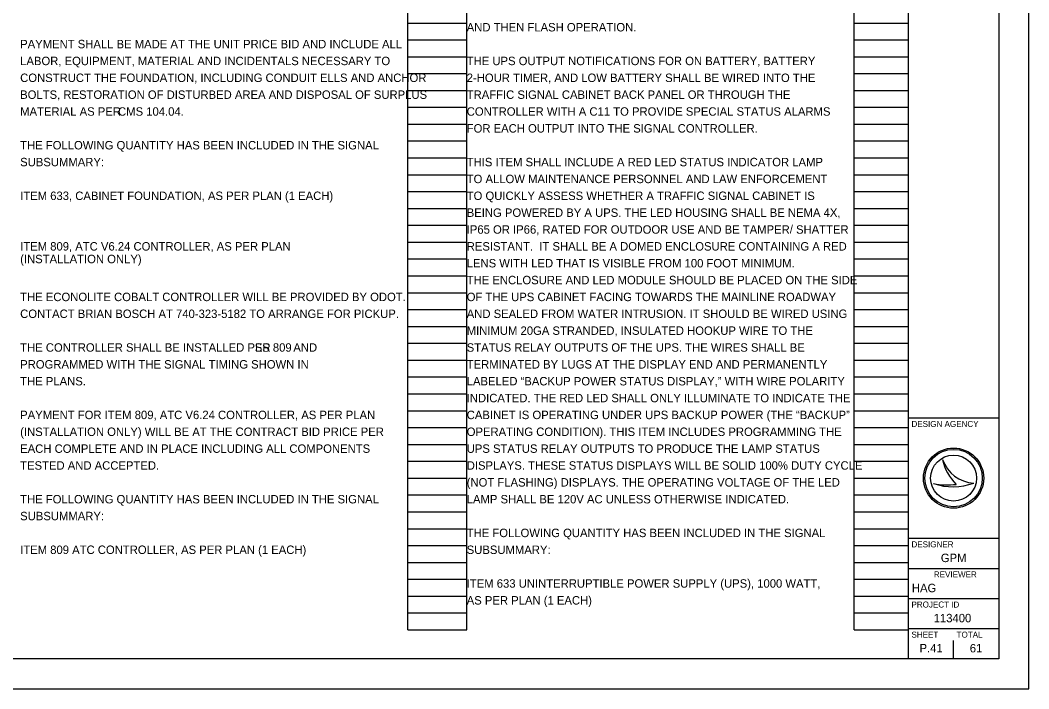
# Model space of a CAD drawing. Extents: x 0 to 34, y 0 to 22.
# Drawn here: x 17.24 to 34, y 0 to 11.11 of the extents above; entities that cross this region are included whole.
import ezdxf

# ---------------------------------------------------------------- set-up
doc = ezdxf.new("R2010")
doc.units = 0
for name, color, linetype in [('SH_Border', 7, 'Continuous'), ('SH_Cut_Line', 7, 'Continuous'), ('SH_Data', 7, 'Continuous'), ('SH_Text', 7, 'Continuous')]:
    doc.layers.add(name, color=color, linetype=linetype)

msp = doc.modelspace()

# ---------------------------------------------------------------- linework, layer by layer
at = {"layer": 'SH_Border'}
for p, q in [((32, 0.5), (32, 21.5)), ((32, 4.5), (33.5, 4.5)), ((32, 2.5), (33.5, 2.5)), ((32, 2), (33.5, 2)), ((32, 1.5), (33.5, 1.5)), ((32, 1), (33.5, 1))]:
    msp.add_line(p, q, dxfattribs=at)
msp.add_lwpolyline([(1.5, 21.5), (33.5, 21.5), (33.5, 0.5), (1.5, 0.5)], close=True, dxfattribs=at)
at = {"layer": 'SH_Cut_Line'}
msp.add_lwpolyline([(0, 0), (34, 0), (34, 22), (0, 22)], close=True, dxfattribs=at)
at = {"layer": 'SH_Data'}
for p, q in [((23.68, 0.98), (23.68, 21.14)), ((24.66, 0.98), (24.66, 21.14)), ((31.1, 0.98), (31.1, 21.14)), ((32, 0.98), (32, 21.14)), ((23.68, 11.06), (24.66, 11.06)), ((31.1, 11.06), (32, 11.06)), ((23.68, 10.78), (24.66, 10.78)), ((31.1, 10.78), (32, 10.78)), ((23.68, 10.5), (24.66, 10.5)), ((31.1, 10.5), (32, 10.5)), ((23.68, 10.22), (24.66, 10.22)), ((31.1, 10.22), (32, 10.22)), ((23.68, 9.94), (24.66, 9.94)), ((31.1, 9.94), (32, 9.94)), ((23.68, 9.66), (24.66, 9.66)), ((31.1, 9.66), (32, 9.66)), ((23.68, 9.38), (24.66, 9.38)), ((31.1, 9.38), (32, 9.38)), ((23.68, 9.1), (24.66, 9.1)), ((31.1, 9.1), (32, 9.1)), ((23.68, 8.82), (24.66, 8.82)), ((31.1, 8.82), (32, 8.82)), ((23.68, 8.54), (24.66, 8.54)), ((31.1, 8.54), (32, 8.54)), ((23.68, 8.26), (24.66, 8.26)), ((31.1, 8.26), (32, 8.26)), ((23.68, 7.98), (24.66, 7.98)), ((31.1, 7.98), (32, 7.98)), ((23.68, 7.7), (24.66, 7.7)), ((31.1, 7.7), (32, 7.7)), ((23.68, 7.42), (24.66, 7.42)), ((31.1, 7.42), (32, 7.42)), ((23.68, 7.14), (24.66, 7.14)), ((31.1, 7.14), (32, 7.14)), ((23.68, 6.86), (24.66, 6.86)), ((31.1, 6.86), (32, 6.86)), ((23.68, 6.58), (24.66, 6.58)), ((31.1, 6.58), (32, 6.58)), ((23.68, 6.3), (24.66, 6.3)), ((31.1, 6.3), (32, 6.3)), ((23.68, 6.02), (24.66, 6.02)), ((31.1, 6.02), (32, 6.02)), ((23.68, 5.74), (24.66, 5.74)), ((31.1, 5.74), (32, 5.74)), ((23.68, 5.46), (24.66, 5.46)), ((31.1, 5.46), (32, 5.46)), ((23.68, 5.18), (24.66, 5.18)), ((31.1, 5.18), (32, 5.18)), ((23.68, 4.9), (24.66, 4.9)), ((31.1, 4.9), (32, 4.9)), ((23.68, 4.62), (24.66, 4.62)), ((31.1, 4.62), (32, 4.62)), ((23.68, 4.34), (24.66, 4.34)), ((31.1, 4.34), (32, 4.34)), ((23.68, 4.06), (24.66, 4.06)), ((31.1, 4.06), (32, 4.06)), ((23.68, 3.78), (24.66, 3.78)), ((31.1, 3.78), (32, 3.78)), ((32.567, 3.81), (32.567, 3.81)), ((23.68, 3.5), (24.66, 3.5)), ((31.1, 3.5), (32, 3.5)), ((32.417, 3.41), (32.417, 3.41)), ((32.75, 3.5), (32.75, 3.5)), ((33.087, 3.419), (33.087, 3.419)), ((23.68, 3.22), (24.66, 3.22)), ((31.1, 3.22), (32, 3.22)), ((23.68, 2.94), (24.66, 2.94)), ((31.1, 2.94), (32, 2.94)), ((23.68, 2.66), (24.66, 2.66)), ((31.1, 2.66), (32, 2.66)), ((23.68, 2.38), (24.66, 2.38)), ((31.1, 2.38), (32, 2.38)), ((23.68, 2.1), (24.66, 2.1)), ((31.1, 2.1), (32, 2.1)), ((23.68, 1.82), (24.66, 1.82)), ((31.1, 1.82), (32, 1.82)), ((23.68, 1.54), (24.66, 1.54)), ((31.1, 1.54), (32, 1.54)), ((23.68, 1.26), (24.66, 1.26)), ((31.1, 1.26), (32, 1.26)), ((23.68, 0.98), (24.66, 0.98)), ((31.1, 0.98), (32, 0.98)), ((32.375, 0.675), (32.375, 0.675)), ((32.75, 0.5), (32.75, 0.8))]:
    msp.add_line(p, q, dxfattribs=at)
for radius in [0.5, 0.477, 0.477, 0.382]:
    msp.add_circle((32.75, 3.5), radius, dxfattribs=at)
for centre, radius, start, end in [((33.116, 3.998), 0.58, 198.9257, 198.9319), ((33.347, 3.97), 0.796, 191.6379, 191.6421), ((33.116, 3.998), 0.58, 198.9319, 267.1657), ((33.347, 3.97), 0.796, 191.6421, 226.0947), ((32.739, 4.37), 1.013, 251.4576, 290.0832), ((32.648, 4.654), 1.266, 259.4964, 259.4995), ((32.739, 4.37), 1.013, 251.4527, 251.4576), ((32.648, 4.654), 1.266, 259.4995, 276.6672)]:
    msp.add_arc(centre, radius, start, end, dxfattribs=at)

# ---------------------------------------------------------------- texts
for s, height, p in [('DESIGN AGENCY', 0.1, (32.05, 4.35)), ('DESIGNER', 0.1, (32.05, 2.35)), ('GPM', 0.14, (32.538, 2.105)), ('REVIEWER', 0.1, (32.422, 1.85)), ('HAG', 0.14, (32.057, 1.605)), ('PROJECT ID', 0.1, (32.05, 1.35)), ('113400', 0.14, (32.419, 1.105)), ('SHEET', 0.1, (32.05, 0.85)), ('TOTAL', 0.1, (32.8, 0.85)), ('P.41', 0.14, (32.184, 0.605)), ('61', 0.14, (33.019, 0.605))]:
    msp.add_text(s, height=height, dxfattribs=at).set_placement(p)
at = {"layer": 'SH_Text'}
for s, p in [('AND THEN FLASH OPERATION. ', (24.66, 10.92)), ('PAYMENT SHALL BE MADE AT THE UNIT PRICE BID AND INCLUDE ALL', (17.24, 10.64)), ('LABOR, EQUIPMENT, MATERIAL AND INCIDENTALS NECESSARY TO', (17.24, 10.36)), ('THE UPS OUTPUT NOTIFICATIONS FOR ON BATTERY, BATTERY', (24.66, 10.36)), ('CONSTRUCT THE FOUNDATION, INCLUDING CONDUIT ELLS AND ANCHOR', (17.24, 10.08)), ('2-HOUR TIMER, AND LOW BATTERY SHALL BE WIRED INTO THE', (24.66, 10.08)), ('BOLTS, RESTORATION OF DISTURBED AREA AND DISPOSAL OF SURPLUS', (17.24, 9.8)), ('TRAFFIC SIGNAL CABINET BACK PANEL OR THROUGH THE', (24.66, 9.8)), ('MATERIAL AS PER ', (17.24, 9.52)), ('CMS 104.04.', (18.867, 9.52)), ('CONTROLLER WITH A C11 TO PROVIDE SPECIAL STATUS ALARMS', (24.66, 9.52)), ('FOR EACH OUTPUT INTO THE SIGNAL CONTROLLER. ', (24.66, 9.24)), ('THE FOLLOWING QUANTITY HAS BEEN INCLUDED IN THE SIGNAL', (17.24, 8.96)), ('SUBSUMMARY:', (17.24, 8.68)), ('THIS ITEM SHALL INCLUDE A RED LED STATUS INDICATOR LAMP', (24.66, 8.68)), ('TO ALLOW MAINTENANCE PERSONNEL AND LAW ENFORCEMENT', (24.66, 8.4)), ('ITEM 633, CABINET FOUNDATION, AS PER PLAN (1 EACH)', (17.24, 8.12)), ('TO QUICKLY ASSESS WHETHER A TRAFFIC SIGNAL CABINET IS', (24.66, 8.12)), ('BEING POWERED BY A UPS. THE LED HOUSING SHALL BE NEMA 4X,', (24.66, 7.84)), ('IP65 OR IP66, RATED FOR OUTDOOR USE AND BE TAMPER/ SHATTER', (24.66, 7.56)), ('ITEM 809, ATC V6.24 CONTROLLER, AS PER PLAN', (17.24, 7.28)), ('RESISTANT.  IT SHALL BE A DOMED ENCLOSURE CONTAINING A RED', (24.66, 7.28)), ('(INSTALLATION ONLY)', (17.24, 7.07)), ('LENS WITH LED THAT IS VISIBLE FROM 100 FOOT MINIMUM.', (24.66, 7)), ('THE ENCLOSURE AND LED MODULE SHOULD BE PLACED ON THE SIDE', (24.66, 6.72)), ('THE ECONOLITE COBALT CONTROLLER WILL BE PROVIDED BY ODOT.', (17.24, 6.44)), ('OF THE UPS CABINET FACING TOWARDS THE MAINLINE ROADWAY', (24.66, 6.44)), ('CONTACT BRIAN BOSCH AT 740-323-5182 TO ARRANGE FOR PICKUP.', (17.24, 6.16)), ('AND SEALED FROM WATER INTRUSION. IT SHOULD BE WIRED USING', (24.66, 6.16)), ('MINIMUM 20GA STRANDED, INSULATED HOOKUP WIRE TO THE', (24.66, 5.88)), ('THE CONTROLLER SHALL BE INSTALLED PER ', (17.24, 5.6)), ('SS 809', (21.137, 5.6)), (' AND ', (21.727, 5.6)), ('STATUS RELAY OUTPUTS OF THE UPS. THE WIRES SHALL BE', (24.66, 5.6)), ('PROGRAMMED WITH THE SIGNAL TIMING SHOWN IN', (17.24, 5.32)), ('TERMINATED BY LUGS AT THE DISPLAY END AND PERMANENTLY', (24.66, 5.32)), ('THE PLANS.', (17.24, 5.04)), ('LABELED “BACKUP POWER STATUS DISPLAY,” WITH WIRE POLARITY', (24.66, 5.04)), ('INDICATED. THE RED LED SHALL ONLY ILLUMINATE TO INDICATE THE', (24.66, 4.76)), ('PAYMENT FOR ITEM 809, ATC V6.24 CONTROLLER, AS PER PLAN', (17.24, 4.48)), ('CABINET IS OPERATING UNDER UPS BACKUP POWER (THE “BACKUP”', (24.66, 4.48)), ('(INSTALLATION ONLY) WILL BE AT THE CONTRACT BID PRICE PER', (17.24, 4.2)), ('OPERATING CONDITION). THIS ITEM INCLUDES PROGRAMMING THE', (24.66, 4.2)), ('EACH COMPLETE AND IN PLACE INCLUDING ALL COMPONENTS', (17.24, 3.92)), ('UPS STATUS RELAY OUTPUTS TO PRODUCE THE LAMP STATUS', (24.66, 3.92)), ('TESTED AND ACCEPTED.', (17.24, 3.64)), ('DISPLAYS. THESE STATUS DISPLAYS WILL BE SOLID 100% DUTY CYCLE', (24.66, 3.64)), ('(NOT FLASHING) DISPLAYS. THE OPERATING VOLTAGE OF THE LED', (24.66, 3.36)), ('THE FOLLOWING QUANTITY HAS BEEN INCLUDED IN THE SIGNAL', (17.24, 3.08)), ('LAMP SHALL BE 120V AC UNLESS OTHERWISE INDICATED.', (24.66, 3.08)), ('SUBSUMMARY:', (17.24, 2.8)), ('THE FOLLOWING QUANTITY HAS BEEN INCLUDED IN THE SIGNAL', (24.66, 2.52)), ('ITEM 809 ATC CONTROLLER, AS PER PLAN (1 EACH)', (17.24, 2.24)), ('SUBSUMMARY:', (24.66, 2.24)), ('ITEM 633 UNINTERRUPTIBLE POWER SUPPLY (UPS), 1000 WATT,', (24.66, 1.68)), ('AS PER PLAN (1 EACH)', (24.66, 1.4))]:
    msp.add_text(s, height=0.14, dxfattribs=at).set_placement(p)

doc.saveas('drawing.dxf')
